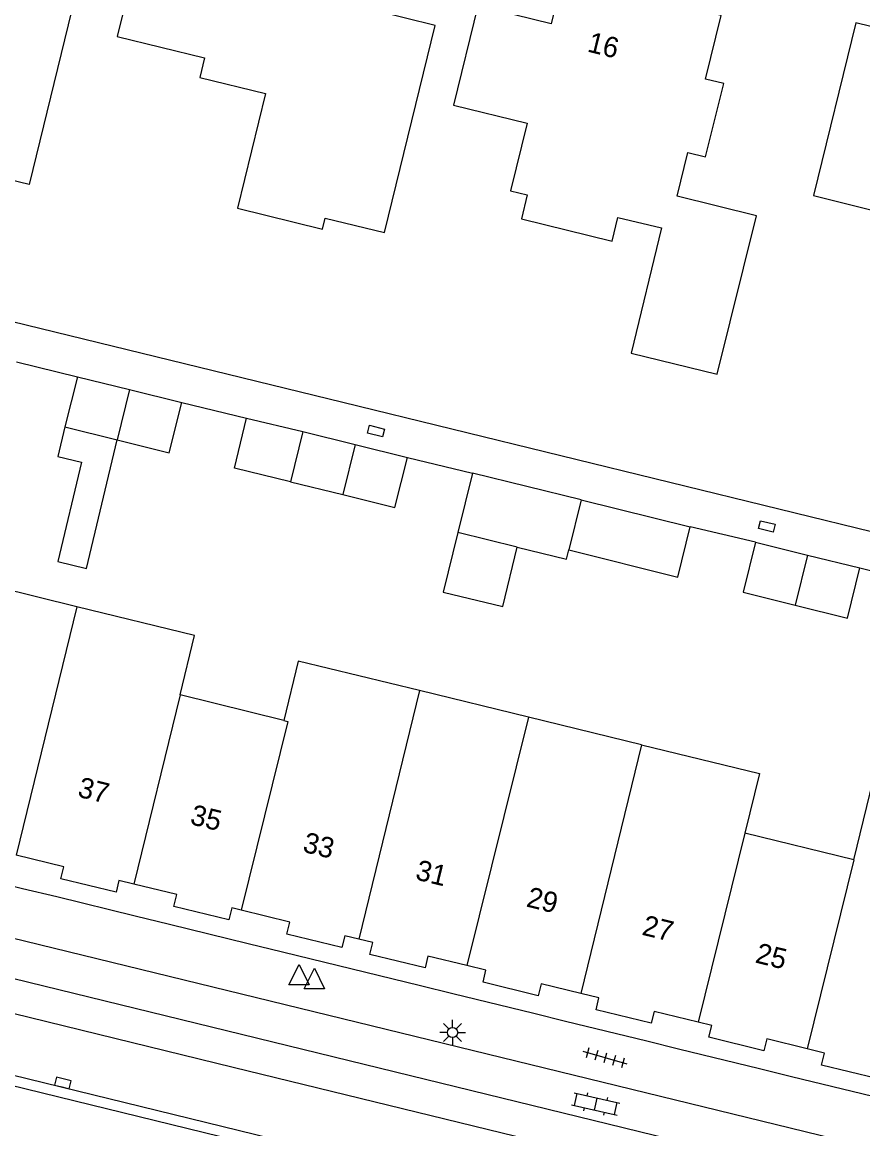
# Model space of a CAD drawing. Extents: x 125000 to 129004, y 397500 to 399008.
# Drawn here: x 126676.8 to 126718, y 398289.9 to 398344.1 of the extents above; entities that cross this region are included whole.
import ezdxf

# ---------------------------------------------------------------- set-up
doc = ezdxf.new("R2010")
doc.units = 0
for name, color, linetype in [('gg-afsc-erfafscheiding', 7, 'Continuous'), ('gg-afsc-muur', 7, 'Continuous'), ('gg-anno-huisnummerreeks BGT', 7, 'Continuous'), ('gg-bbg-bijgebouw', 7, 'Continuous'), ('gg-bbg-gedigitaliseerde bebouwing', 7, 'Continuous'), ('gg-bbg-gedigitaliseerde bijgebouw', 7, 'Continuous'), ('gg-bbg-hoofdgebouw', 7, 'Continuous'), ('gg-bbg-luifel en loopbrug', 7, 'Continuous'), ('gg-bbg-tussenscheiding', 7, 'Continuous'), ('gg-knt-verharding', 7, 'Continuous'), ('gg-knt-verharding nz', 7, 'Continuous'), ('gt-symb-klinker verharding', 7, 'Continuous'), ('gt-symb-kolk', 7, 'Continuous'), ('gt-symb-kolk center center', 7, 'Continuous'), ('gt-symb-lichtmast', 7, 'Continuous'), ('gt-symb-tegel verharding', 7, 'Continuous'), ('gt-symb-waterafsluiter', 7, 'Continuous')]:
    doc.layers.add(name, color=color, linetype=linetype)

# ---------------------------------------------------------------- blocks, each defined once
blk = doc.blocks.new('gt0-KOLKCC')
at = {"layer": 'gt-symb-kolk center center'}
blk.add_lwpolyline([(-0.375, 0.2), (0.375, 0.2), (0.375, -0.2), (-0.375, -0.2)], close=True, dxfattribs=at)
blk = doc.blocks.new('gt0-WAFSL')
at = {"layer": 'gt-symb-waterafsluiter'}
for p, q in [((-0.5, -0.333), (0, 0.667)), ((0, 0.667), (0.5, -0.333)), ((0.5, -0.333), (-0.5, -0.333))]:
    blk.add_line(p, q, dxfattribs=at)
blk = doc.blocks.new('gt0-KL1')
at = {"layer": 'gt-symb-klinker verharding'}
for p, q in [((-1.15, 0.3), (1.15, 0.3)), ((-1, -0.3), (-1, 0.3)), ((-0.5, 0.3), (-0.5, 0.45)), ((0, -0.3), (0, 0.3)), ((0.5, 0.3), (0.5, 0.45)), ((1, -0.3), (1, 0.3)), ((-1.15, -0.3), (1.15, -0.3)), ((-0.5, -0.45), (-0.5, -0.3)), ((0.5, -0.45), (0.5, -0.3))]:
    blk.add_line(p, q, dxfattribs=at)
blk = doc.blocks.new('gt0-TEG1')
at = {"layer": 'gt-symb-tegel verharding'}
for p, q in [((-1.125, 0), (1.125, 0)), ((-0.9, -0.25), (-0.9, 0.25)), ((-0.45, -0.25), (-0.45, 0.25)), ((0, -0.25), (0, 0.25)), ((0.45, -0.25), (0.45, 0.25)), ((0.9, -0.25), (0.9, 0.25))]:
    blk.add_line(p, q, dxfattribs=at)
blk = doc.blocks.new('gt0-KOLK')
at = {"layer": 'gt-symb-kolk'}
blk.add_lwpolyline([(0, 0), (0.375, 0), (0.375, 0.4), (-0.375, 0.4), (-0.375, 0), (0, 0)], dxfattribs=at)
blk = doc.blocks.new('gt0-LMAST')
at = {"layer": 'gt-symb-lichtmast'}
for p, q in [((-0.005, 0.246), (-0.005, 0.621)), ((-0.182, 0.173), (-0.447, 0.438)), ((0.172, 0.173), (0.437, 0.438)), ((-0.255, -0.004), (-0.63, -0.004)), ((-0.182, -0.181), (-0.447, -0.446)), ((-0.005, -0.254), (-0.005, -0.629)), ((0.437, -0.446), (0.172, -0.181)), ((0.245, -0.004), (0.62, -0.004))]:
    blk.add_line(p, q, dxfattribs=at)
blk.add_circle((-0.005, -0.004), 0.25, dxfattribs=at)

msp = doc.modelspace()

# ---------------------------------------------------------------- linework, layer by layer
at = {"layer": 'gg-afsc-erfafscheiding'}
msp.add_line((126712.707, 398318.632), (126709.51, 398319.377), dxfattribs=at)
at = {"layer": 'gg-afsc-muur'}
for p, q in [((126675.491, 398329.646), (126692.484, 398325.497)), ((126672.931, 398302.626), (126676.788, 398301.675)), ((126678.469, 398301.278), (126682.316, 398300.331)), ((126684, 398299.924), (126687.853, 398298.978)), ((126689.532, 398298.572), (126696.295, 398296.916)), ((126697.878, 398296.529), (126701.839, 398295.554)), ((126703.399, 398295.17), (126707.376, 398294.206)), ((126708.941, 398293.815), (126712.909, 398292.851)), ((126714.473, 398292.465), (126718.456, 398291.49))]:
    msp.add_line(p, q, dxfattribs=at)
at = {"layer": 'gg-bbg-bijgebouw'}
for p, q in [((126679.477, 398326.739), (126678.868, 398324.284)), ((126679.477, 398326.739), (126682.034, 398326.105)), ((126682.034, 398326.105), (126684.59, 398325.471)), ((126678.868, 398324.284), (126681.425, 398323.65)), ((126690.529, 398324.05), (126689.923, 398321.594)), ((126690.529, 398324.05), (126693.089, 398323.419)), ((126693.089, 398323.419), (126695.648, 398322.788)), ((126689.923, 398321.594), (126692.483, 398320.963)), ((126712.707, 398318.632), (126715.263, 398318)), ((126715.263, 398318), (126717.818, 398317.369))]:
    msp.add_line(p, q, dxfattribs=at)
for points in [[(126681.425, 398323.65), (126683.982, 398323.016), (126684.59, 398325.471)], [(126692.483, 398320.963), (126695.042, 398320.332), (126695.648, 398322.788)], [(126712.707, 398318.632), (126712.1, 398316.176), (126714.656, 398315.544)], [(126714.656, 398315.544), (126717.211, 398314.913), (126717.818, 398317.369)]]:
    msp.add_lwpolyline(points, dxfattribs=at)
at = {"layer": 'gg-bbg-gedigitaliseerde bebouwing'}
msp.add_lwpolyline([(126717.525, 398303.075), (126718.475, 398306.961), (126723.995, 398305.612), (126723.045, 398301.726)], dxfattribs=at)
at = {"layer": 'gg-bbg-gedigitaliseerde bijgebouw'}
for p, q in [((126698.834, 398322.014), (126698.123, 398319.103)), ((126704.164, 398320.705), (126698.834, 398322.014)), ((126704.164, 398320.705), (126709.51, 398319.377)), ((126701.037, 398318.388), (126698.123, 398319.103)), ((126708.911, 398316.919), (126709.51, 398319.377)), ((126703.554, 398318.25), (126708.911, 398316.919))]:
    msp.add_line(p, q, dxfattribs=at)
msp.add_lwpolyline([(126701.037, 398318.388), (126703.444, 398317.8), (126703.554, 398318.25)], dxfattribs=at)
at = {"layer": 'gg-bbg-hoofdgebouw'}
for p, q in [((126679.447, 398315.472), (126673.909, 398316.824)), ((126689.592, 398309.897), (126684.509, 398311.152)), ((126701.592, 398310.056), (126696.24, 398311.363)), ((126707.116, 398308.708), (126701.592, 398310.056)), ((126717.525, 398303.075), (126712.191, 398304.38))]:
    msp.add_line(p, q, dxfattribs=at)
for points in [[(126667.99, 398355.978), (126669.062, 398355.716), (126669.245, 398356.463), (126676.064, 398354.795), (126675.882, 398354.048), (126677.482, 398353.657), (126676.729, 398350.577), (126680.415, 398349.676), (126677.109, 398336.153), (126672.298, 398337.315), (126673.476, 398342.112)], [(126687.319, 398335.002), (126691.497, 398333.972), (126691.623, 398334.501), (126694.526, 398333.801), (126697.018, 398343.946), (126694.098, 398344.663), (126695.293, 398349.53), (126687.904, 398351.345), (126687.618, 398350.175), (126683.341, 398351.222), (126682.519, 398347.868), (126681.995, 398347.996), (126681.716, 398346.855), (126682.24, 398346.727), (126681.427, 398343.407), (126685.709, 398342.358), (126685.473, 398341.397), (126688.692, 398340.609), (126687.319, 398335.002)], [(126700.7, 398335.845), (126701.525, 398335.644), (126701.237, 398334.479), (126705.688, 398333.38), (126705.97, 398334.546), (126708.108, 398334.029), (126706.621, 398327.886), (126710.838, 398326.865), (126712.765, 398334.616), (126708.863, 398335.576), (126709.391, 398337.722), (126710.267, 398337.506), (126711.151, 398341.097), (126710.265, 398341.315), (126711.034, 398344.438), (126708.611, 398345.035), (126708.901, 398346.212), (126703.559, 398347.524), (126702.699, 398344.022), (126699.11, 398344.904), (126697.915, 398340.041), (126701.514, 398339.157), (126700.7, 398335.845)], [(126717.628, 398344.072), (126715.558, 398335.617), (126723.873, 398333.54), (126723.069, 398330.308), (126724.465, 398329.976), (126723.133, 398324.461), (126727.988, 398323.286), (126729.42, 398329.138), (126726.321, 398329.898), (126727.034, 398332.807), (126727.122, 398332.786), (126729.199, 398341.257), (126717.628, 398344.072)], [(126684.509, 398311.152), (126685.22, 398314.067), (126679.447, 398315.472)], [(126696.24, 398311.363), (126690.303, 398312.812), (126689.592, 398309.897)], [(126707.116, 398308.708), (126712.904, 398307.295), (126712.191, 398304.38)], [(126682.252, 398301.884), (126681.514, 398302.064), (126681.372, 398301.481), (126678.667, 398302.138), (126678.811, 398302.721), (126676.481, 398303.297)], [(126687.511, 398300.601), (126687.049, 398300.714), (126686.907, 398300.131), (126684.204, 398300.79), (126684.346, 398301.372), (126682.252, 398301.884)], [(126693.274, 398299.184), (126692.589, 398299.353), (126692.445, 398298.77), (126689.746, 398299.436), (126689.889, 398300.02), (126687.511, 398300.601)], [(126698.57, 398297.891), (126696.657, 398298.35), (126696.521, 398297.786), (126693.812, 398298.441), (126693.958, 398299.015), (126693.274, 398299.184)], [(126704.148, 398296.527), (126702.203, 398296.996), (126702.058, 398296.414), (126699.359, 398297.084), (126699.499, 398297.668), (126698.57, 398297.891)], [(126709.903, 398295.123), (126707.739, 398295.648), (126707.596, 398295.065), (126704.893, 398295.729), (126705.034, 398296.313), (126704.148, 398296.527)], [(126715.235, 398293.81), (126713.26, 398294.298), (126713.117, 398293.715), (126710.423, 398294.377), (126710.565, 398294.962), (126709.903, 398295.123)], [(126720.78, 398292.464), (126718.798, 398292.949), (126718.658, 398292.366), (126715.939, 398293.018), (126716.083, 398293.6), (126715.235, 398293.81)]]:
    msp.add_lwpolyline(points, dxfattribs=at)
at = {"layer": 'gg-bbg-luifel en loopbrug'}
msp.add_line((126687.767, 398324.711), (126690.529, 398324.05), dxfattribs=at)
for points in [[(126689.923, 398321.594), (126687.178, 398322.251), (126687.767, 398324.711)], [(126678.868, 398324.284), (126678.519, 398322.825), (126679.686, 398322.546), (126678.523, 398317.683), (126679.917, 398317.349), (126681.425, 398323.65)], [(126698.123, 398319.103), (126697.41, 398316.185), (126700.325, 398315.474), (126701.037, 398318.388)]]:
    msp.add_lwpolyline(points, dxfattribs=at)
at = {"layer": 'gg-bbg-tussenscheiding'}
for p, q in [((126682.034, 398326.105), (126681.425, 398323.65)), ((126693.089, 398323.419), (126692.483, 398320.963)), ((126704.164, 398320.705), (126703.554, 398318.25)), ((126715.263, 398318), (126714.656, 398315.544)), ((126679.447, 398315.472), (126676.481, 398303.297)), ((126684.509, 398311.152), (126682.252, 398301.884)), ((126696.24, 398311.363), (126693.274, 398299.184)), ((126701.592, 398310.056), (126698.57, 398297.891)), ((126707.116, 398308.708), (126704.148, 398296.527)), ((126712.191, 398304.38), (126709.903, 398295.123)), ((126717.525, 398303.075), (126715.235, 398293.81))]:
    msp.add_line(p, q, dxfattribs=at)
msp.add_lwpolyline([(126689.592, 398309.897), (126689.793, 398309.847), (126687.511, 398300.601)], dxfattribs=at)
at = {"layer": 'gg-knt-verharding'}
for p, q in [((126676.49, 398327.461), (126679.477, 398326.739)), ((126684.59, 398325.471), (126687.767, 398324.711)), ((126692.484, 398325.497), (126764.278, 398307.911)), ((126695.648, 398322.788), (126698.834, 398322.014)), ((126717.818, 398317.369), (126723.795, 398315.889)), ((126651.7, 398303.292), (126756.379, 398277.708)), ((126676.788, 398301.675), (126678.469, 398301.278)), ((126682.316, 398300.331), (126684, 398299.924)), ((126687.853, 398298.978), (126689.532, 398298.572)), ((126696.295, 398296.916), (126697.878, 398296.529)), ((126701.839, 398295.554), (126703.399, 398295.17)), ((126707.376, 398294.206), (126708.941, 398293.815)), ((126712.909, 398292.851), (126714.473, 398292.465))]:
    msp.add_line(p, q, dxfattribs=at)
for points in [[(126651.7, 398303.292), (126652.12, 398305.149), (126756.884, 398279.581), (126756.379, 398277.708)], [(126648.389, 398299.367), (126713.638, 398283.392), (126746.702, 398275.349), (126755.36, 398273.213)], [(126648.271, 398298.881), (126713.519, 398282.906), (126746.583, 398274.863), (126755.241, 398272.727)]]:
    msp.add_lwpolyline(points, dxfattribs=at)
at = {"layer": 'gg-knt-verharding nz'}
msp.add_lwpolyline([(126757.715, 398275.675), (126687.106, 398292.898), (126632.302, 398306.326), (126553.993, 398325.483)], dxfattribs=at)

# ---------------------------------------------------------------- block references
at = {"layer": 'gt-symb-klinker verharding', "rotation": -12.590950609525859}
msp.add_blockref('gt0-KL1', (126704.881, 398291.106), dxfattribs=at)
at = {"layer": 'gt-symb-kolk', "rotation": -13.772145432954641}
msp.add_blockref('gt0-KOLK', (126678.718, 398291.945), dxfattribs=at)
at = {"layer": 'gt-symb-kolk center center'}
for p, rotation in [((126694.108, 398324.075), 165.82485794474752), ((126713.263, 398319.402), 166.29711003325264)]:
    msp.add_blockref('gt0-KOLKCC', p, dxfattribs=dict(at, rotation=rotation))
at = {"layer": 'gt-symb-lichtmast'}
msp.add_blockref('gt0-LMAST', (126697.87, 398294.619), dxfattribs=at)
at = {"layer": 'gt-symb-tegel verharding', "rotation": 163.92082762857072}
msp.add_blockref('gt0-TEG1', (126705.34, 398293.366), dxfattribs=at)
at = {"layer": 'gt-symb-waterafsluiter'}
for p in [(126690.341, 398297.281), (126691.095, 398297.09)]:
    msp.add_blockref('gt0-WAFSL', p, dxfattribs=at)

# ---------------------------------------------------------------- texts
at = {"layer": 'gg-anno-huisnummerreeks BGT'}
for s, rotation, p in [('16', 346.2, (126704.423, 398342.677)), ('37', 346.2, (126679.444, 398306.175)), ('35', 346.3, (126684.956, 398304.827)), ('33', 346.2, (126690.474, 398303.476)), ('31', 346.3, (126695.997, 398302.121)), ('29', 346.3, (126701.435, 398300.793)), ('27', 346.3, (126707.1, 398299.409)), ('25', 346.2, (126712.65, 398298.05))]:
    msp.add_text(s, height=1, rotation=rotation, dxfattribs=at).set_placement(p)

doc.saveas('drawing.dxf')
